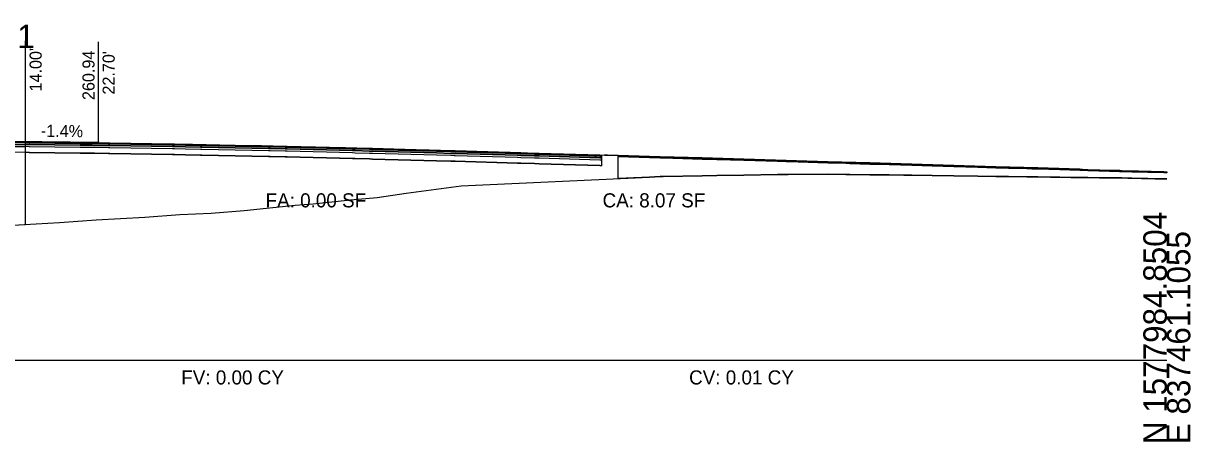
# Model space of a CAD drawing. Extents: x -26 to 6303, y -16 to 9563.
# Drawn here: x 2163.7 to 2302.8, y 3990.3 to 4040.1 of the extents above; entities that cross this region are included whole.
import ezdxf

# ---------------------------------------------------------------- set-up
doc = ezdxf.new("R2010")
doc.units = 0
for name, color, linetype in [('ASPHALT_19MM1', 7, 'Continuous'), ('ASPHALT_9_5MM1', 7, 'Continuous'), ('CONST_DCH', 7, 'Continuous'), ('CONST_LV3', 7, 'Continuous'), ('Default', 7, 'Continuous'), ('DTM_P_FINISHED_GRADE', 7, 'Continuous'), ('DTM_P_FINISHED_GRADE2', 7, 'Continuous'), ('DTM_X_GROUND', 7, 'Continuous'), ('TRANS_EOP_PAVED', 7, 'Continuous'), ('TRANS_PAVED_SHOULDERS', 7, 'Continuous'), ('XS_CELL', 7, 'Continuous'), ('XS_M_SHAPES_EARTHWORK', 7, 'Continuous'), ('XS_P_ASPHALT', 7, 'Continuous'), ('XS_P_GROUND', 7, 'Continuous'), ('XS_P_SUBGRADE_GRANULAR', 7, 'Continuous'), ('XS_P_SUBGRADE_LEVELING', 7, 'Continuous'), ('XS_P_SUBGRADE_MILLING', 7, 'Continuous'), ('XS_P_TX_CLEARZONE', 7, 'Continuous'), ('XS_P_TX_FS_BS', 7, 'Continuous'), ('XS_SHEET_EW_TX_AREA', 7, 'Continuous'), ('XS_SHEET_EW_TX_VOLUME', 7, 'Continuous')]:
    doc.layers.add(name, color=color, linetype=linetype)

msp = doc.modelspace()

# ---------------------------------------------------------------- linework, layer by layer
at = {"layer": 'ASPHALT_19MM1'}
for points in [[(2136, 4024.76), (2136, 4024.67), (2140.63, 4024.8), (2150, 4025.06), (2154.63, 4025.19), (2164, 4025.46), (2164, 4025.55), (2164, 4025.73), (2154.63, 4025.47), (2150, 4025.34), (2140.63, 4025.07), (2136, 4024.94), (2136, 4024.76)], [(2181.76, 4025.46), (2183.06, 4025.43), (2184.85, 4025.4), (2185, 4025.39), (2192.96, 4025.23), (2193.15, 4025.22), (2194.92, 4025.18), (2195.16, 4025.18), (2202.97, 4024.99), (2203.27, 4024.98), (2204.99, 4024.93), (2205.35, 4024.92), (2212.98, 4024.71), (2214.67, 4024.66), (2215.09, 4024.65), (2215.19, 4024.65), (2222.62, 4024.43), (2223.01, 4024.41), (2224.65, 4024.37), (2225.21, 4024.35), (2232.44, 4024.13), (2232.64, 4024.13), (2232.64, 4023.86), (2232.44, 4023.86), (2225.21, 4024.08), (2224.65, 4024.09), (2223.01, 4024.14), (2222.62, 4024.16), (2215.19, 4024.37), (2215.09, 4024.38), (2214.67, 4024.39), (2212.98, 4024.44), (2205.35, 4024.65), (2204.99, 4024.66), (2203.27, 4024.7), (2202.97, 4024.71), (2195.16, 4024.9), (2194.92, 4024.91), (2193.15, 4024.95), (2192.96, 4024.96), (2185, 4025.12), (2184.85, 4025.13), (2183.06, 4025.16), (2181.76, 4025.18), (2181.65, 4025.19), (2181.63, 4025.19), (2181.63, 4025.19), (2181.52, 4025.19), (2174.04, 4025.32), (2173.92, 4025.32), (2173.87, 4025.32), (2172.2, 4025.34), (2171.93, 4025.35), (2171.81, 4025.35), (2171.13, 4025.36), (2170.51, 4025.37), (2164.46, 4025.45), (2164.43, 4025.45), (2164, 4025.46), (2164, 4025.73), (2164.43, 4025.72), (2164.46, 4025.72), (2170.51, 4025.64), (2171.13, 4025.63), (2171.81, 4025.62), (2171.93, 4025.62), (2172.2, 4025.61), (2173.87, 4025.59), (2173.92, 4025.59), (2174.04, 4025.59), (2181.52, 4025.46), (2181.63, 4025.46), (2181.63, 4025.46), (2181.65, 4025.46), (2181.76, 4025.46)]]:
    msp.add_lwpolyline(points, dxfattribs=at)
at = {"layer": 'ASPHALT_9_5MM1'}
for points in [[(2136, 4025.19), (2136, 4025.15), (2140.63, 4025.28), (2150, 4025.54), (2154.63, 4025.67), (2164, 4025.94), (2164, 4025.98), (2164, 4026.06), (2154.63, 4025.8), (2150, 4025.67), (2140.63, 4025.41), (2136, 4025.28), (2136, 4025.19)], [(2181.76, 4025.79), (2183.06, 4025.76), (2184.85, 4025.73), (2185, 4025.73), (2192.96, 4025.56), (2193.15, 4025.55), (2194.92, 4025.52), (2195.16, 4025.51), (2202.97, 4025.32), (2203.27, 4025.31), (2204.99, 4025.27), (2205.35, 4025.26), (2212.98, 4025.04), (2214.67, 4025), (2215.09, 4024.98), (2215.19, 4024.98), (2222.62, 4024.76), (2223.01, 4024.75), (2224.65, 4024.7), (2225.21, 4024.68), (2232.44, 4024.47), (2232.64, 4024.46), (2232.64, 4024.34), (2232.44, 4024.34), (2225.21, 4024.56), (2224.65, 4024.57), (2223.01, 4024.62), (2222.62, 4024.63), (2215.19, 4024.85), (2215.09, 4024.86), (2214.67, 4024.87), (2212.98, 4024.92), (2205.35, 4025.13), (2204.99, 4025.14), (2203.27, 4025.18), (2202.97, 4025.19), (2195.16, 4025.38), (2194.92, 4025.39), (2193.15, 4025.43), (2192.96, 4025.43), (2185, 4025.6), (2184.85, 4025.61), (2183.06, 4025.64), (2181.76, 4025.66), (2181.65, 4025.67), (2181.63, 4025.67), (2181.63, 4025.67), (2181.52, 4025.67), (2174.04, 4025.8), (2173.92, 4025.8), (2173.87, 4025.8), (2172.2, 4025.82), (2171.93, 4025.83), (2171.81, 4025.83), (2171.13, 4025.84), (2170.51, 4025.85), (2164.46, 4025.93), (2164.43, 4025.93), (2164, 4025.94), (2164, 4026.06), (2164.43, 4026.06), (2164.46, 4026.06), (2170.51, 4025.97), (2171.13, 4025.96), (2171.81, 4025.95), (2171.93, 4025.95), (2172.2, 4025.95), (2173.87, 4025.92), (2173.92, 4025.92), (2174.04, 4025.92), (2181.52, 4025.79), (2181.63, 4025.79), (2181.63, 4025.79), (2181.65, 4025.79), (2181.76, 4025.79)]]:
    msp.add_lwpolyline(points, dxfattribs=at)
at = {"layer": 'CONST_LV3'}
for points in [[(2172.7, 4025.94), (2165.93, 4026.03), (2164, 4026.06), (2161.06, 4025.98), (2150, 4025.67)], [(2181.76, 4025.79), (2183.06, 4025.76), (2184.85, 4025.73), (2185, 4025.73), (2192.96, 4025.56), (2193.15, 4025.55), (2194.92, 4025.52), (2195.16, 4025.51), (2202.97, 4025.32), (2203.27, 4025.31), (2204.99, 4025.27), (2205.35, 4025.26), (2212.98, 4025.04), (2214.67, 4025), (2215.09, 4024.98), (2215.19, 4024.98), (2222.62, 4024.76), (2223.01, 4024.75), (2224.65, 4024.7), (2225.21, 4024.68), (2232.44, 4024.47), (2232.64, 4024.46), (2232.64, 4023.19), (2232.44, 4023.2), (2225.21, 4023.41), (2224.65, 4023.43), (2223.01, 4023.48), (2222.62, 4023.49), (2215.19, 4023.71), (2215.09, 4023.71), (2214.67, 4023.73), (2212.98, 4023.77), (2205.35, 4023.98), (2204.99, 4024), (2203.27, 4024.04), (2202.97, 4024.05), (2195.16, 4024.24), (2194.92, 4024.25), (2193.15, 4024.28), (2192.96, 4024.29), (2185, 4024.45), (2184.85, 4024.46), (2183.06, 4024.49), (2181.76, 4024.52), (2181.65, 4024.52), (2181.63, 4024.52), (2181.63, 4024.52), (2181.52, 4024.52), (2174.04, 4024.65), (2173.92, 4024.65), (2173.87, 4024.65), (2172.2, 4024.68), (2171.93, 4024.68), (2171.81, 4024.68), (2171.13, 4024.69), (2170.51, 4024.7), (2164.46, 4024.78), (2164.43, 4024.78), (2164, 4024.79), (2164, 4026.06), (2164.43, 4026.06), (2164.46, 4026.06), (2170.51, 4025.97), (2171.13, 4025.96), (2171.81, 4025.95), (2171.93, 4025.95), (2172.2, 4025.95), (2173.87, 4025.92), (2173.92, 4025.92), (2174.04, 4025.92), (2181.52, 4025.79), (2181.63, 4025.79), (2181.63, 4025.79), (2181.65, 4025.79), (2181.76, 4025.79)], [(2289.63, 4022.78), (2284.63, 4022.93), (2279.63, 4023.07), (2274.62, 4023.22), (2269.62, 4023.37), (2264.62, 4023.52), (2259.62, 4023.66), (2254.62, 4023.81), (2249.61, 4023.96), (2244.61, 4024.11), (2239.61, 4024.26), (2234.61, 4024.4), (2233.35, 4024.44), (2232.93, 4024.45)]]:
    msp.add_lwpolyline(points, dxfattribs=at)
at = {"layer": 'Default'}
msp.add_lwpolyline([(2172.7, 4025.94), (2173.88, 4025.92), (2173.94, 4025.92), (2174.05, 4025.92), (2178.74, 4025.84), (2180.61, 4025.81), (2180.7, 4025.81), (2180.72, 4025.81), (2180.81, 4025.81), (2183.36, 4025.76), (2183.91, 4025.75), (2190.43, 4025.61), (2192.02, 4025.58), (2192.11, 4025.58), (2194.92, 4025.52), (2194.92, 4025.52), (2194.94, 4025.52), (2194.97, 4025.51), (2195.06, 4025.51), (2195.16, 4025.51), (2201.94, 4025.34), (2201.98, 4025.34), (2202.01, 4025.34), (2202.12, 4025.34), (2204.87, 4025.27), (2204.99, 4025.27), (2204.99, 4025.27), (2205.04, 4025.27), (2205.08, 4025.26), (2205.21, 4025.26), (2211.84, 4025.08), (2211.98, 4025.07), (2211.98, 4025.07), (2211.99, 4025.07), (2212.02, 4025.07), (2212.02, 4025.07), (2212.06, 4025.07), (2212.1, 4025.07), (2214.78, 4024.99), (2214.9, 4024.99), (2215.09, 4024.98), (2215.09, 4024.98), (2215.19, 4024.98), (2221.65, 4024.79), (2221.67, 4024.79), (2221.69, 4024.79), (2221.77, 4024.78), (2222.04, 4024.78), (2222.04, 4024.78), (2224.65, 4024.7), (2224.74, 4024.7), (2224.82, 4024.69), (2225.01, 4024.69), (2225.2, 4024.68), (2231.49, 4024.5), (2231.5, 4024.5), (2231.5, 4024.5), (2231.7, 4024.49), (2232.04, 4024.13)], dxfattribs=at)
at = {"layer": 'DTM_P_FINISHED_GRADE'}
msp.add_lwpolyline([(2164, 4026.06), (2164.43, 4026.06), (2164.46, 4026.06), (2170.51, 4025.97), (2171.13, 4025.96), (2171.81, 4025.95), (2171.93, 4025.95), (2172.2, 4025.95), (2173.87, 4025.92), (2173.92, 4025.92), (2174.04, 4025.92), (2181.52, 4025.79), (2181.63, 4025.79), (2181.63, 4025.79), (2181.65, 4025.79), (2181.76, 4025.79), (2183.06, 4025.76), (2184.85, 4025.73), (2185, 4025.73), (2192.96, 4025.56), (2193.15, 4025.55), (2194.92, 4025.52), (2195.16, 4025.51), (2202.97, 4025.32), (2203.27, 4025.31), (2204.99, 4025.27), (2205.35, 4025.26), (2212.98, 4025.04), (2214.67, 4025), (2215.09, 4024.98), (2215.19, 4024.98), (2222.62, 4024.76), (2223.01, 4024.75), (2224.65, 4024.7), (2225.21, 4024.68), (2232.44, 4024.47), (2232.64, 4024.46)], dxfattribs=at)
at = {"layer": 'DTM_P_FINISHED_GRADE2'}
msp.add_lwpolyline([(2160.89, 4025.97), (2164, 4026.06), (2164.43, 4026.06), (2164.46, 4026.06), (2170.51, 4025.97), (2171.13, 4025.96), (2171.93, 4025.95), (2172.2, 4025.95), (2173.87, 4025.92), (2173.92, 4025.92), (2174.04, 4025.92), (2181.52, 4025.79), (2181.63, 4025.79), (2181.65, 4025.79), (2181.76, 4025.79), (2183.06, 4025.76), (2184.85, 4025.73), (2185, 4025.73), (2192.96, 4025.56), (2193.15, 4025.55), (2194.92, 4025.52), (2195.16, 4025.51), (2202.97, 4025.32), (2203.27, 4025.31), (2204.99, 4025.27), (2205.35, 4025.26), (2212.98, 4025.04), (2213.02, 4025.04), (2214.7, 4025), (2215.09, 4024.98), (2215.19, 4024.98), (2222.62, 4024.76), (2223.01, 4024.75), (2224.65, 4024.7), (2225.21, 4024.68), (2225.89, 4024.66), (2233.04, 4024.45), (2234.61, 4024.4), (2235.35, 4024.38), (2239.61, 4024.26), (2240.42, 4024.23), (2244.61, 4024.11), (2245.5, 4024.08), (2249.61, 4023.96), (2250.58, 4023.93), (2254.62, 4023.81), (2255.67, 4023.78), (2259.62, 4023.66), (2260.76, 4023.63), (2264.62, 4023.52), (2265.86, 4023.48), (2269.62, 4023.37), (2270.97, 4023.33), (2274.61, 4023.22), (2274.62, 4023.22), (2274.62, 4023.22), (2276.09, 4023.18), (2279.63, 4023.07), (2280.78, 4023.04), (2283.31, 4022.96), (2283.74, 4022.95), (2284.63, 4022.93), (2286.36, 4022.87), (2289.63, 4022.78), (2289.97, 4022.77), (2290.57, 4022.75), (2292, 4022.71), (2294.38, 4022.64), (2294.48, 4022.63), (2294.63, 4022.63), (2296.61, 4022.57), (2299.64, 4022.48), (2300, 4022.47)], dxfattribs=at)
at = {"layer": 'DTM_X_GROUND'}
msp.add_lwpolyline([(2162.48, 4016.12), (2168.06, 4016.42), (2172.42, 4016.75), (2178.21, 4017.05), (2182.37, 4017.36), (2186.1, 4017.55), (2190.06, 4017.85), (2196.13, 4018.47), (2198.27, 4018.66), (2202.71, 4019.12), (2205.9, 4019.4), (2209.37, 4019.9), (2215.91, 4020.79), (2238.36, 4021.84), (2240.11, 4021.93), (2253.62, 4022.12), (2259.91, 4022.18), (2262.1, 4022.14), (2262.56, 4022.13), (2268.66, 4022.06), (2276.43, 4021.97), (2278.8, 4021.93), (2286.12, 4021.84), (2288.56, 4021.8), (2295.34, 4021.72), (2298.63, 4021.64), (2300, 4021.62)], dxfattribs=at)
at = {"layer": 'TRANS_PAVED_SHOULDERS'}
for points in [[(2136, 4025.01), (2136, 4024.94), (2140.63, 4025.07), (2150, 4025.34), (2154.63, 4025.47), (2164, 4025.73), (2164, 4025.8), (2164, 4025.94), (2154.63, 4025.67), (2150, 4025.54), (2140.63, 4025.28), (2136, 4025.15), (2136, 4025.01)], [(2181.76, 4025.66), (2183.06, 4025.64), (2184.85, 4025.61), (2185, 4025.6), (2192.96, 4025.43), (2193.15, 4025.43), (2194.92, 4025.39), (2195.16, 4025.38), (2202.97, 4025.19), (2203.27, 4025.18), (2204.99, 4025.14), (2205.35, 4025.13), (2212.98, 4024.92), (2214.67, 4024.87), (2215.09, 4024.86), (2215.19, 4024.85), (2222.62, 4024.63), (2223.01, 4024.62), (2224.65, 4024.57), (2225.21, 4024.56), (2232.44, 4024.34), (2232.64, 4024.34), (2232.64, 4024.13), (2232.44, 4024.13), (2225.21, 4024.35), (2224.65, 4024.37), (2223.01, 4024.41), (2222.62, 4024.43), (2215.19, 4024.65), (2215.09, 4024.65), (2214.67, 4024.66), (2212.98, 4024.71), (2205.35, 4024.92), (2204.99, 4024.93), (2203.27, 4024.98), (2202.97, 4024.99), (2195.16, 4025.18), (2194.92, 4025.18), (2193.15, 4025.22), (2192.96, 4025.23), (2185, 4025.39), (2184.85, 4025.4), (2183.06, 4025.43), (2181.76, 4025.46), (2181.65, 4025.46), (2181.63, 4025.46), (2181.63, 4025.46), (2181.52, 4025.46), (2174.04, 4025.59), (2173.92, 4025.59), (2173.87, 4025.59), (2172.2, 4025.61), (2171.93, 4025.62), (2171.81, 4025.62), (2171.13, 4025.63), (2170.51, 4025.64), (2164.46, 4025.72), (2164.43, 4025.72), (2164, 4025.73), (2164, 4025.94), (2164.43, 4025.93), (2164.46, 4025.93), (2170.51, 4025.85), (2171.13, 4025.84), (2171.81, 4025.83), (2171.93, 4025.83), (2172.2, 4025.82), (2173.87, 4025.8), (2173.92, 4025.8), (2174.04, 4025.8), (2181.52, 4025.67), (2181.63, 4025.67), (2181.63, 4025.67), (2181.65, 4025.67), (2181.76, 4025.66)]]:
    msp.add_lwpolyline(points, dxfattribs=at)
at = {"layer": 'XS_CELL'}
msp.add_line((2150, 4000), (2300, 4000), dxfattribs=at)
at = {"layer": 'XS_M_SHAPES_EARTHWORK'}
msp.add_lwpolyline([(2162.48, 4016.12), (2164, 4016.2), (2164, 4025.46), (2154.63, 4025.19)], dxfattribs=at)
at = {"layer": 'XS_P_ASPHALT'}
for points in [[(2164, 4026.06), (2164.43, 4026.06), (2164.46, 4026.06), (2170.51, 4025.97), (2171.13, 4025.96), (2171.81, 4025.95), (2171.93, 4025.95), (2172.2, 4025.95), (2173.87, 4025.92), (2173.92, 4025.92), (2174.04, 4025.92), (2181.52, 4025.79), (2181.63, 4025.79), (2181.63, 4025.79), (2181.65, 4025.79), (2181.76, 4025.79), (2183.06, 4025.76), (2184.85, 4025.73), (2185, 4025.73), (2192.96, 4025.56), (2193.15, 4025.55), (2194.92, 4025.52), (2195.16, 4025.51), (2202.97, 4025.32), (2203.27, 4025.31), (2204.99, 4025.27), (2205.35, 4025.26), (2212.98, 4025.04), (2214.67, 4025), (2215.09, 4024.98), (2215.19, 4024.98), (2222.62, 4024.76), (2223.01, 4024.75), (2224.65, 4024.7), (2225.21, 4024.68), (2232.44, 4024.47), (2232.64, 4024.46)], [(2300, 4022.47), (2300, 4022.35), (2300, 4022.35), (2299.64, 4022.36), (2299.64, 4022.36), (2296.61, 4022.45), (2296.61, 4022.45), (2294.63, 4022.5), (2294.63, 4022.5), (2294.48, 4022.51), (2294.48, 4022.51), (2294.38, 4022.51), (2294.38, 4022.51), (2292, 4022.58), (2292, 4022.58), (2290.57, 4022.62), (2290.57, 4022.62), (2289.97, 4022.64), (2289.97, 4022.64), (2289.63, 4022.65), (2289.63, 4022.65), (2286.36, 4022.75), (2286.36, 4022.75), (2284.63, 4022.8), (2284.63, 4022.8), (2283.74, 4022.83), (2283.74, 4022.83), (2283.31, 4022.84), (2283.31, 4022.84), (2280.78, 4022.91), (2280.78, 4022.91), (2279.63, 4022.95), (2279.63, 4022.95), (2276.09, 4023.05), (2276.09, 4023.05), (2274.62, 4023.1), (2274.62, 4023.1), (2274.62, 4023.1), (2274.62, 4023.1), (2274.61, 4023.1), (2274.61, 4023.1), (2270.97, 4023.2), (2270.97, 4023.2), (2269.62, 4023.24), (2269.62, 4023.24), (2265.86, 4023.35), (2265.86, 4023.35), (2264.62, 4023.39), (2264.62, 4023.39), (2260.76, 4023.51), (2260.76, 4023.51), (2259.62, 4023.54), (2259.62, 4023.54), (2255.67, 4023.66), (2255.67, 4023.66), (2254.62, 4023.69), (2254.62, 4023.69), (2250.58, 4023.81), (2250.58, 4023.81), (2249.61, 4023.84), (2249.61, 4023.84), (2245.5, 4023.96), (2245.5, 4023.96), (2244.61, 4023.98), (2244.61, 4023.98), (2240.42, 4024.11), (2240.42, 4024.11), (2239.61, 4024.13), (2239.61, 4024.13), (2235.35, 4024.26), (2235.35, 4024.26), (2234.61, 4024.28), (2234.61, 4024.28), (2234.61, 4024.3), (2234.61, 4024.3), (2234.61, 4024.4), (2234.61, 4024.4), (2235.35, 4024.38), (2235.35, 4024.38), (2239.61, 4024.26), (2239.61, 4024.26), (2240.42, 4024.23), (2240.42, 4024.23), (2244.61, 4024.11), (2244.61, 4024.11), (2245.5, 4024.08), (2245.5, 4024.08), (2249.61, 4023.96), (2249.61, 4023.96), (2250.58, 4023.93), (2250.58, 4023.93), (2254.62, 4023.81), (2254.62, 4023.81), (2255.67, 4023.78), (2255.67, 4023.78), (2259.62, 4023.66), (2259.62, 4023.66), (2260.76, 4023.63), (2260.76, 4023.63), (2264.62, 4023.52), (2264.62, 4023.52), (2265.86, 4023.48), (2265.86, 4023.48), (2269.62, 4023.37), (2269.62, 4023.37), (2270.97, 4023.33), (2270.97, 4023.33), (2274.61, 4023.22), (2274.61, 4023.22), (2274.62, 4023.22), (2274.62, 4023.22), (2274.62, 4023.22), (2274.62, 4023.22), (2276.09, 4023.18), (2276.09, 4023.18), (2279.63, 4023.07), (2279.63, 4023.07), (2280.78, 4023.04), (2280.78, 4023.04), (2283.31, 4022.96), (2283.31, 4022.96), (2283.74, 4022.95), (2283.74, 4022.95), (2284.63, 4022.93), (2284.63, 4022.93), (2286.36, 4022.87), (2286.36, 4022.87), (2289.63, 4022.78), (2289.63, 4022.78), (2289.97, 4022.77), (2289.97, 4022.77), (2290.57, 4022.75), (2290.57, 4022.75), (2292, 4022.71), (2292, 4022.71), (2294.38, 4022.64), (2294.38, 4022.64), (2294.48, 4022.63), (2294.48, 4022.63), (2294.63, 4022.63), (2294.63, 4022.63), (2296.61, 4022.57), (2296.61, 4022.57), (2299.64, 4022.48), (2299.64, 4022.48), (2300, 4022.47)]]:
    msp.add_lwpolyline(points, dxfattribs=at)
at = {"layer": 'XS_P_GROUND'}
msp.add_lwpolyline([(2172.7, 4025.94), (2172.7, 4025.94), (2172.7, 4025.94), (2172.7, 4025.94)], dxfattribs=at)
at = {"layer": 'XS_P_SUBGRADE_GRANULAR'}
for points in [[(2164, 4024.79), (2154.63, 4024.53), (2150, 4024.4)], [(2164, 4024.79), (2164.43, 4024.78), (2164.46, 4024.78), (2170.51, 4024.7), (2171.13, 4024.69), (2171.81, 4024.68), (2171.93, 4024.68), (2172.2, 4024.68), (2173.87, 4024.65), (2173.92, 4024.65), (2174.04, 4024.65), (2181.52, 4024.52), (2181.63, 4024.52), (2181.63, 4024.52), (2181.65, 4024.52), (2181.76, 4024.52), (2183.06, 4024.49), (2184.85, 4024.46), (2185, 4024.45), (2192.96, 4024.29), (2193.15, 4024.28), (2194.92, 4024.25), (2195.16, 4024.24), (2202.97, 4024.05), (2203.27, 4024.04), (2204.99, 4024), (2205.35, 4023.98), (2212.98, 4023.77), (2214.67, 4023.73), (2215.09, 4023.71), (2215.19, 4023.71), (2222.62, 4023.49), (2223.01, 4023.48), (2224.65, 4023.43), (2225.21, 4023.41), (2232.44, 4023.2), (2232.64, 4023.19)]]:
    msp.add_lwpolyline(points, dxfattribs=at)
at = {"layer": 'XS_P_SUBGRADE_LEVELING'}
msp.add_lwpolyline([(2300, 4021.62), (2299.64, 4021.62), (2295.85, 4021.71), (2294.63, 4021.73), (2294.57, 4021.73), (2294.38, 4021.73), (2293.18, 4021.75), (2290.57, 4021.78), (2290.11, 4021.79), (2289.63, 4021.79), (2287.25, 4021.83), (2284.63, 4021.86), (2283.92, 4021.87), (2283.31, 4021.88), (2281.14, 4021.9), (2279.63, 4021.92), (2277.49, 4021.95), (2274.62, 4021.99), (2274.62, 4021.99), (2274.61, 4021.99), (2272.05, 4022.02), (2269.62, 4022.05), (2266.9, 4022.08), (2264.62, 4022.11), (2262.23, 4022.14), (2261.76, 4022.14), (2259.62, 4022.17), (2254.89, 4022.13), (2254.62, 4022.13), (2253.62, 4022.12), (2249.61, 4022.06), (2246.38, 4022.02), (2244.61, 4021.99), (2239.98, 4021.91), (2239.61, 4021.9), (2238.36, 4021.84), (2234.61, 4021.67), (2234.61, 4022.56), (2234.61, 4024.28), (2238.36, 4024.17), (2239.61, 4024.13), (2239.98, 4024.12), (2244.61, 4023.98), (2246.38, 4023.93), (2249.61, 4023.84), (2253.62, 4023.72), (2254.62, 4023.69), (2254.89, 4023.68), (2259.62, 4023.54), (2261.76, 4023.48), (2262.23, 4023.46), (2264.62, 4023.39), (2266.9, 4023.32), (2269.62, 4023.24), (2272.05, 4023.17), (2274.61, 4023.1), (2274.62, 4023.1), (2274.62, 4023.1), (2277.49, 4023.01), (2279.63, 4022.95), (2281.14, 4022.9), (2283.31, 4022.84), (2283.92, 4022.82), (2284.63, 4022.8), (2287.25, 4022.72), (2289.63, 4022.65), (2290.11, 4022.64), (2290.57, 4022.62), (2293.18, 4022.55), (2294.38, 4022.51), (2294.57, 4022.51), (2294.63, 4022.5), (2295.85, 4022.47), (2299.64, 4022.36), (2300, 4022.35)], dxfattribs=at)
at = {"layer": 'XS_P_SUBGRADE_MILLING'}
msp.add_lwpolyline([(2300, 4021.62), (2299.64, 4021.62), (2295.85, 4021.71), (2294.63, 4021.73), (2294.57, 4021.73), (2294.38, 4021.73), (2293.18, 4021.75), (2290.57, 4021.78), (2290.11, 4021.79), (2289.63, 4021.79), (2287.25, 4021.83), (2284.63, 4021.86), (2283.92, 4021.87), (2283.31, 4021.88), (2281.14, 4021.9), (2279.63, 4021.92), (2277.49, 4021.95), (2274.62, 4021.99), (2274.62, 4021.99), (2274.61, 4021.99), (2272.05, 4022.02), (2269.62, 4022.05), (2266.9, 4022.08), (2264.62, 4022.11), (2262.23, 4022.14), (2261.76, 4022.14), (2259.62, 4022.17), (2254.89, 4022.13), (2254.62, 4022.13), (2253.62, 4022.12), (2249.61, 4022.06), (2246.38, 4022.02), (2244.61, 4021.99), (2239.98, 4021.91), (2239.61, 4021.9), (2238.36, 4021.84), (2234.61, 4021.67), (2234.61, 4021.67), (2234.61, 4021.67), (2238.36, 4021.84), (2239.61, 4021.9), (2239.98, 4021.91), (2244.61, 4021.99), (2246.38, 4022.02), (2249.61, 4022.06), (2253.62, 4022.12), (2254.62, 4022.13), (2254.89, 4022.13), (2259.62, 4022.17), (2261.76, 4022.14), (2262.23, 4022.14), (2264.62, 4022.11), (2266.9, 4022.08), (2269.62, 4022.05), (2272.05, 4022.02), (2274.61, 4021.99), (2274.62, 4021.99), (2274.62, 4021.99), (2277.49, 4021.95), (2279.63, 4021.92), (2281.14, 4021.9), (2283.31, 4021.88), (2283.92, 4021.87), (2284.63, 4021.86), (2287.25, 4021.83), (2289.63, 4021.79), (2290.11, 4021.79), (2290.57, 4021.78), (2293.18, 4021.75), (2294.38, 4021.73), (2294.57, 4021.73), (2294.63, 4021.73), (2295.85, 4021.71), (2299.64, 4021.62), (2300, 4021.62)], dxfattribs=at)
at = {"layer": 'XS_P_TX_CLEARZONE'}
for p, q in [((2164, 4026.06), (2164, 4038.06)), ((2172.7, 4025.94), (2172.7, 4037.94))]:
    msp.add_line(p, q, dxfattribs=at)

# ---------------------------------------------------------------- texts
at = {"layer": 'CONST_DCH'}
msp.add_text('X', height=0.24, dxfattribs=at).set_placement((2163.92, 4025.94))
at = {"layer": 'TRANS_EOP_PAVED'}
msp.add_text('X', height=0.24, dxfattribs=at).set_placement((2172.63, 4025.82))
at = {"layer": 'XS_CELL'}
msp.add_text('1243+41.05 / 1', height=2.8, dxfattribs=at).set_placement((2140, 4037.2))
for s, p in [('N 1577984.8504', (2300, 3990)), ('E 837461.1055', (2302.8, 3990))]:
    msp.add_text(s, height=2.8, rotation=90, dxfattribs=at).set_placement(p)
at = {"layer": 'XS_P_TX_CLEARZONE'}
for s, p in [("14.00'", (2165.92, 4032.03)), ('260.94', (2172.22, 4031.01)), ("22.70'", (2174.62, 4031.66))]:
    msp.add_text(s, height=1.44, rotation=90, dxfattribs=at).set_placement(p)
at = {"layer": 'XS_P_TX_FS_BS'}
msp.add_text('-1.4%', height=1.44, rotation=359.2121, dxfattribs=at).set_placement((2165.81, 4026.64))
at = {"layer": 'XS_SHEET_EW_TX_AREA'}
for s, p in [('FA: 0.00 SF', (2192.6, 4018.22)), ('CA: 8.07 SF', (2232.76, 4018.22))]:
    msp.add_text(s, height=1.68, dxfattribs=at).set_placement(p)
at = {"layer": 'XS_SHEET_EW_TX_VOLUME'}
for s, p in [('FV: 0.00 CY', (2182.55, 3997.12)), ('CV: 0.01 CY', (2243.07, 3997.12))]:
    msp.add_text(s, height=1.68, dxfattribs=at).set_placement(p)

doc.saveas('drawing.dxf')
